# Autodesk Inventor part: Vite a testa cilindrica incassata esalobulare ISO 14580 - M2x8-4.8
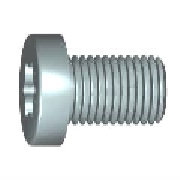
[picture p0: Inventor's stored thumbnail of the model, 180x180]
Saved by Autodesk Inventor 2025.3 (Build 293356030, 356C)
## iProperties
Created: 2024-01
Part Number: Vite a testa cilindrica incassata esalobulare ISO 14580 - M2x8-4.8
Material: Acciaio
Description: ISO 14580 - Viti a testa cilindrica incassata esalobulare - Seconda edizione
Document SubType Name: Modeling
Standard: 14580
Designer: R5800u
Standards Organization: ISO
Language: it-IT
Size Designation: M2x8-4.8
Categories: <MemberInstance><Categories><Category DisplayName="Elementi di fissaggio" InternalName="e4da775c-781d-43d5-af7c-5136215cf5a6" Mnemonic="FSTN"><Category DisplayN
Density: 7.85 g/cm^3
Appearance: Lamiera
IsCustomPart: 0
Author: R5800u
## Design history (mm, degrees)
revolve "Revolution1" stored, may be unused: angle "d4" = 90 deg
thread "Thread1" dims "d6" = 8 (= b), "d7" = 0
sketch "Sketch2" dims "d21" = 1.75 (= A_)
  geometry: L1 (-0.53, -0.306)-(-0.875, 0); L2 (0, 0)-(-0.53, -0.306); L3 (0, 0)-(-0.53, 0.306); L4 (-2.85, 0)-(2.85, 0) reference; L5 (-0.875, 0)-(-0.53, 0.306); A1 r 0.613 centre (0, 0) between (-0.53, -0.306) and (-0.53, 0.306); 2 further points
  constraints: 8 end point, 2 coincident, 2 point on circle, 1 centre point, 1 horizontal alignment, 1 point on line, 2 other
  dimensions: "d19" = 60 deg angle of L3 L2; "d20" = 30 deg angle of L3 L4 (= 0.5 x d19); "d26" = 1.225 diameter of A1 (= 0.7 x d21)
extrude "Extrusion1" cut sketch "Sketch2" distance "d27" = 0.84 (= t); taper "d28" = 0 deg
pattern_circular "Circular Pattern1" dims angle "d30" = 360 deg
fillet "Fillet2" dims "d32" = 0.2 (= v)
fillet "Fillet3" dims "d33" = 0.2 (= v)
fillet "Fillet5" dims "d35" = 0.1 (= r)
chamfer "Chamfer2" distance "d36" = 0.2 (= v); stored, may be unused: second distance "d37" = 2, angle "d38" = 45 deg
body "Solid1"
sketch "Sketch1"
  geometry: L1 (0, 0)-(8, 0); L2 (8, 0)-(8, 1); L3 (8, 1)-(0, 1); L4 (0, 1)-(0, 0); L5 (0, 0)-(-1.55, 0); L6 (-1.55, 0)-(-1.55, 1.9); L7 (-1.55, 1.9)-(0, 2.036); L8 (0, 2.036)-(0, 0)
  constraints: 16 end point, 3 parallel, 2 horizontal, 2 perpendicular
  dimensions: "d0" = 2 diameter of L3 L1 (= d); "d3" = 8 distance of L2.end L3.end (= l_); "d46" = 85 deg angle of L8 L7; "d47" = 1.55 distance between parallel lines of L8 L6 (= k); "d49" = 3.8 diameter of L6.end L1 (= dk)
other parameters: "A_" = 1.75 [user parameter; used in 1 equation term], "d" = 2 [user parameter; used in 2 equation terms], "dk" = 3.8 [user parameter; used in 1 equation term], "k" = 1.55 [user parameter; used in 1 equation term], "l_" = 8 [user parameter; used in 2 equation terms], "lg" = 0 [user parameter; used in 1 equation term], "t" = 0.84 [user parameter; used in 1 equation term], "w" = 0.55 [user parameter], "v" = 0.2 [user parameter; used in 3 equation terms], "r" = 0.1 [user parameter; used in 1 equation term], "da" = 2.6 [user parameter], "ds_" = 2 (= d) [user parameter], "ls" = 0 [user parameter], "b" = 8 (= l_ - lg) [user parameter; used in 1 equation term], "d42" = 0, "d43" = 0, "d44" = 0, "p" = 0.4 [user parameter]
